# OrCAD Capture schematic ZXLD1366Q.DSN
size Custom; title: ZXLD1366Q,HIGH ACCURACY 1A, 60V LED DRIVER; rev: 1.0; note: DS37078 Rev. 2 - 2
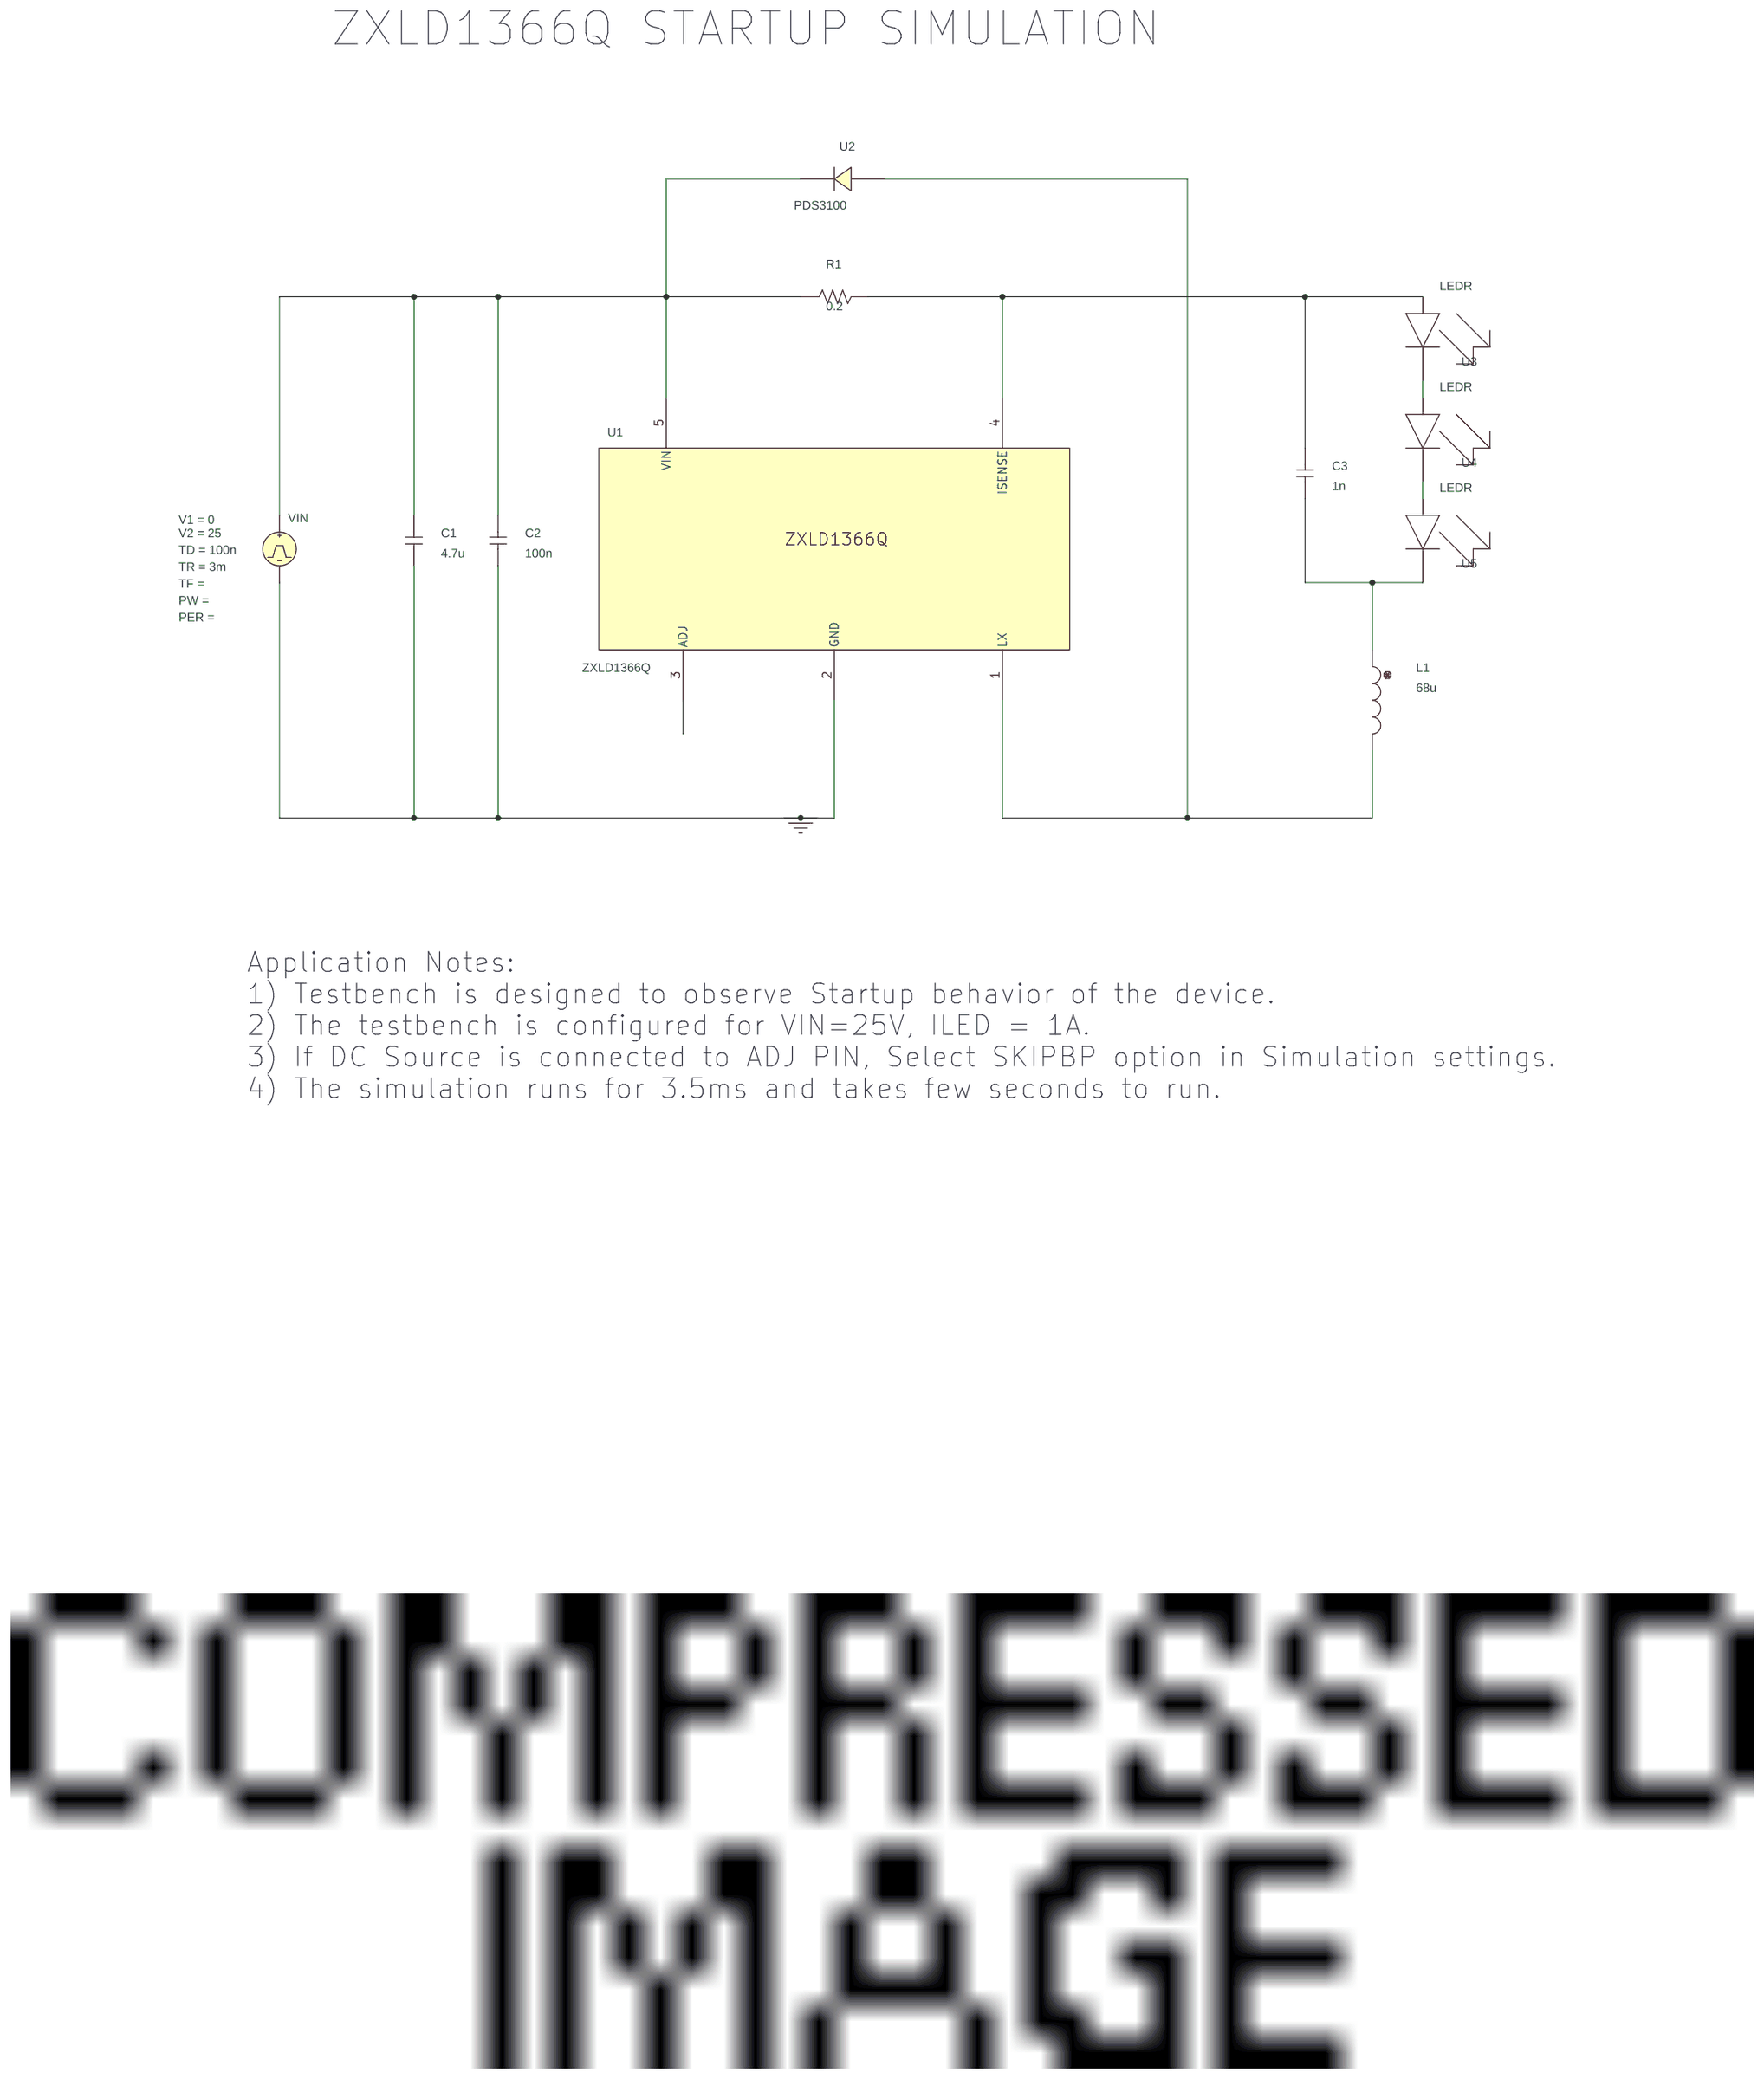
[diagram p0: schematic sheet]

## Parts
C1  4.7u  [RAD/CK05]
C2  100n  [RAD/CK05]
C3  1n  [RAD/CK05]
L1  68u  [DISC/.350x.175/LS.200x.100/.034]
R1  0.2  [AX/RC05]
U1  ZXLD1366Q
U2  PDS3100
U3  LEDR
U4  LEDR
U5  LEDR
VIN  VPULSE

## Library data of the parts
C1-C3 = C
L1 = L
R1 = R
U1 = ZXLD1366Q
U2 = PDS3100
U3-U5 = LEDR
VIN = VPULSE: TD: 100n; TR: 3m; V1: 0; V2: 25

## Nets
0: C1.1 C2.1 U1.2(GND) VIN.2(-)
N19966: C1.2 C2.2 R1.1 U1.5(VIN) U2.2(B) VIN.1(+)
N20096: C3.2 R1.2 U1.4(ISENSE) U3.1(A)
N20112: L1.2 U1.1(LX) U2.1(A)
N20146: U3.2(B) U4.1(A)
N20156: C3.1 L1.1 U5.2(B)
N20454: U4.2(B) U5.1(A)

Not connected (* = marked no-connect by the designer): U1 3(ADJ)

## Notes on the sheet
- ZXLD1366Q STARTUP SIMULATION
- Application Notes:
  1) Testbench is designed to observe Startup behavior of the device.
  2) The testbench is configured for VIN=25V, ILED = 1A.
  3) If DC Source is connected to ADJ PIN, Select SKIPBP option in Simulation settings.
  4) The simulation runs for 3.5ms and takes few seconds to run.
